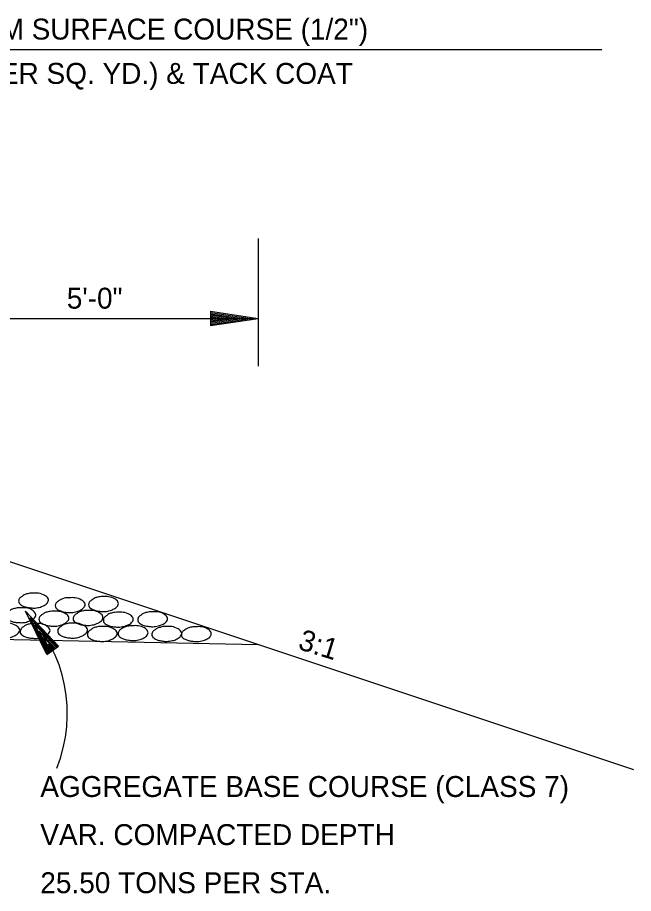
# Model space of a CAD drawing. Extents: x 1035 to 3550, y 35 to 1510.
# Drawn here: x 2578.4 to 2755, y 575.8 to 826.9 of the extents above; entities that cross this region are included whole.
import ezdxf

# ---------------------------------------------------------------- set-up
doc = ezdxf.new("R2010")
doc.units = 0
doc.layers.add('Default', color=7, linetype='Continuous')

msp = doc.modelspace()

# ---------------------------------------------------------------- linework, layer by layer
at = {"layer": 'Default'}
for p, q in [((2745.94, 817.63), (2512.84, 817.63)), ((2647.44, 763.6), (2647.44, 726.95)), ((2633.76, 742.69), (2647.44, 740.65)), ((2633.76, 742.69), (2633.76, 738.59)), ((2633.76, 742.36), (2645.15, 740.65)), ((2633.76, 742), (2642.78, 740.65)), ((2633.76, 741.67), (2640.49, 740.65)), ((2633.76, 741.3), (2638.18, 740.65)), ((2633.76, 740.97), (2635.89, 740.65)), ((2557.51, 740.65), (2647.44, 740.65)), ((2633.76, 738.59), (2647.44, 740.65)), ((2633.76, 739.96), (2638.18, 740.65)), ((2633.76, 739.27), (2642.78, 740.65)), ((2633.76, 738.93), (2645.15, 740.65)), ((2633.76, 739.63), (2640.49, 740.65)), ((2633.76, 740.32), (2635.89, 740.65)), ((2557.51, 677.18), (2755.04, 611.33)), ((2586.85, 644.27), (2580.73, 656.69)), ((2590.23, 646.64), (2580.73, 656.69)), ((2261.14, 654.92), (2647.44, 647.2)), ((2587.13, 644.45), (2582.05, 654.82)), ((2589.95, 646.4), (2582.05, 654.82)), ((2589.66, 646.23), (2583.39, 652.87)), ((2587.43, 644.66), (2583.39, 652.87)), ((2587.72, 644.86), (2584.68, 651)), ((2589.37, 646.01), (2584.68, 651)), ((2589.09, 645.83), (2586.02, 649.1)), ((2588, 645.08), (2586.02, 649.1)), ((2586.85, 644.27), (2590.23, 646.64)), ((2588.8, 645.62), (2587.32, 647.24)), ((2588.28, 645.25), (2587.32, 647.24))]:
    msp.add_line(p, q, dxfattribs=at)
msp.add_arc((2550.89, 627.38), 41.83, 337.9932, 44.4822, dxfattribs=at)
for points in [[(2582.95, 661.87), (2584.48, 661.86), (2586.3, 661.22), (2587.19, 660.39), (2587.31, 659.85), (2586.85, 658.93), (2586.33, 658.54), (2585.33, 658.02), (2583.87, 657.68), (2583.11, 657.6), (2582, 657.71), (2580.74, 657.92), (2579.79, 658.29), (2578.91, 659.02), (2578.76, 659.6), (2579.02, 660.42), (2579.72, 660.95), (2580.36, 661.37), (2581.38, 661.72), (2582.01, 661.86), (2582.95, 661.87)], [(2593.44, 660.57), (2594.95, 660.56), (2596.77, 659.92), (2597.69, 659.06), (2597.83, 658.56), (2597.33, 657.63), (2596.81, 657.21), (2595.84, 656.72), (2594.33, 656.35), (2593.59, 656.3), (2592.46, 656.38), (2591.24, 656.6), (2590.29, 656.99), (2589.4, 657.69), (2589.26, 658.31), (2589.53, 659.09), (2590.21, 659.65), (2590.87, 660.09), (2591.85, 660.42), (2592.47, 660.56), (2593.44, 660.57)], [(2603.01, 660.88), (2604.52, 660.86), (2606.36, 660.24), (2607.23, 659.38), (2607.37, 658.88), (2606.89, 657.93), (2606.38, 657.53), (2605.38, 657.04), (2603.91, 656.67), (2603.15, 656.62), (2602.04, 656.7), (2600.8, 656.92), (2599.83, 657.31), (2598.94, 658.01), (2598.82, 658.59), (2599.1, 659.41), (2599.79, 659.96), (2600.41, 660.39), (2601.42, 660.74), (2602.06, 660.86), (2603.01, 660.88)], [(2579.33, 657.67), (2580.81, 657.66), (2582.65, 657.03), (2583.52, 656.16), (2583.68, 655.66), (2583.21, 654.73), (2582.67, 654.32), (2581.68, 653.84), (2580.22, 653.46), (2579.44, 653.42), (2578.35, 653.48), (2577.1, 653.68), (2576.15, 654.09), (2575.26, 654.79), (2575.12, 655.38), (2575.4, 656.21), (2576.09, 656.77), (2576.7, 657.2), (2577.73, 657.5), (2578.37, 657.66), (2579.33, 657.67)], [(2588.77, 656.68), (2590.28, 656.67), (2592.1, 656.03), (2593.02, 655.17), (2593.16, 654.67), (2592.66, 653.74), (2592.14, 653.32), (2591.17, 652.84), (2589.66, 652.46), (2588.93, 652.41), (2587.79, 652.49), (2586.57, 652.71), (2585.62, 653.1), (2584.73, 653.8), (2584.59, 654.42), (2584.86, 655.2), (2585.54, 655.76), (2586.2, 656.2), (2587.18, 656.53), (2587.8, 656.67), (2588.77, 656.68)], [(2598.59, 656.9), (2600.1, 656.88), (2601.94, 656.26), (2602.82, 655.38), (2602.94, 654.89), (2602.49, 653.97), (2601.96, 653.53), (2600.96, 653.06), (2599.48, 652.7), (2598.75, 652.63), (2597.61, 652.72), (2596.36, 652.92), (2595.44, 653.31), (2594.53, 654.01), (2594.4, 654.61), (2594.68, 655.43), (2595.35, 655.98), (2595.99, 656.43), (2597, 656.74), (2597.64, 656.88), (2598.59, 656.9)], [(2607.26, 656.39), (2608.75, 656.38), (2610.56, 655.75), (2611.47, 654.88), (2611.62, 654.4), (2611.14, 653.46), (2610.59, 653.03), (2609.61, 652.58), (2608.13, 652.22), (2607.38, 652.14), (2606.29, 652.23), (2605.03, 652.44), (2604.09, 652.81), (2603.18, 653.51), (2603.05, 654.12), (2603.33, 654.94), (2604.02, 655.49), (2604.64, 655.93), (2605.65, 656.22), (2606.31, 656.38), (2607.26, 656.39)], [(2617.09, 656.51), (2618.6, 656.5), (2620.44, 655.89), (2621.33, 655.02), (2621.47, 654.53), (2620.98, 653.57), (2620.45, 653.16), (2619.46, 652.71), (2617.98, 652.34), (2617.24, 652.27), (2616.11, 652.35), (2614.87, 652.56), (2613.94, 652.94), (2613.02, 653.66), (2612.91, 654.24), (2613.18, 655.05), (2613.85, 655.61), (2614.5, 656.05), (2615.5, 656.37), (2616.14, 656.5), (2617.09, 656.51)], [(2574.66, 653.27), (2576.17, 653.26), (2577.99, 652.62), (2578.91, 651.76), (2579.05, 651.26), (2578.55, 650.33), (2578.02, 649.91), (2577.06, 649.42), (2575.55, 649.05), (2574.81, 649), (2573.68, 649.08), (2572.46, 649.3), (2571.51, 649.69), (2570.62, 650.39), (2570.48, 651.01), (2570.75, 651.79), (2571.43, 652.35), (2572.09, 652.79), (2573.07, 653.12), (2573.69, 653.26), (2574.66, 653.27)], [(2583.37, 653.19), (2584.88, 653.17), (2586.7, 652.53), (2587.62, 651.67), (2587.76, 651.17), (2587.26, 650.24), (2586.73, 649.82), (2585.77, 649.34), (2584.25, 648.96), (2583.52, 648.92), (2582.38, 648.99), (2581.17, 649.21), (2580.22, 649.6), (2579.33, 650.3), (2579.19, 650.93), (2579.46, 651.7), (2580.14, 652.27), (2580.8, 652.7), (2581.78, 653.03), (2582.4, 653.17), (2583.37, 653.19)], [(2594.12, 653.27), (2595.63, 653.26), (2597.46, 652.62), (2598.38, 651.76), (2598.52, 651.26), (2598.02, 650.33), (2597.49, 649.91), (2596.52, 649.42), (2595.01, 649.05), (2594.28, 649), (2593.14, 649.08), (2591.92, 649.3), (2590.97, 649.69), (2590.09, 650.39), (2589.95, 651.01), (2590.21, 651.79), (2590.9, 652.35), (2591.55, 652.79), (2592.53, 653.12), (2593.16, 653.26), (2594.12, 653.27)], [(2602.64, 652.31), (2604.15, 652.3), (2605.98, 651.66), (2606.89, 650.8), (2607.03, 650.3), (2606.54, 649.37), (2606.01, 648.95), (2605.04, 648.46), (2603.53, 648.09), (2602.8, 648.04), (2601.66, 648.12), (2600.44, 648.34), (2599.49, 648.73), (2598.6, 649.43), (2598.46, 650.05), (2598.73, 650.83), (2599.41, 651.39), (2600.07, 651.83), (2601.05, 652.16), (2601.67, 652.3), (2602.64, 652.31)], [(2611.5, 652.55), (2613.01, 652.53), (2614.82, 651.91), (2615.74, 651.03), (2615.85, 650.55), (2615.39, 649.6), (2614.86, 649.2), (2613.88, 648.71), (2612.39, 648.34), (2611.64, 648.28), (2610.52, 648.39), (2609.29, 648.59), (2608.32, 648.96), (2607.45, 649.69), (2607.29, 650.27), (2607.56, 651.08), (2608.26, 651.64), (2608.9, 652.06), (2609.92, 652.39), (2610.53, 652.53), (2611.5, 652.55)], [(2621.14, 652.31), (2622.64, 652.3), (2624.46, 651.66), (2625.38, 650.82), (2625.51, 650.29), (2625.02, 649.37), (2624.48, 648.95), (2623.53, 648.45), (2622.01, 648.14), (2621.28, 648.03), (2620.14, 648.15), (2618.93, 648.35), (2617.99, 648.74), (2617.09, 649.43), (2616.93, 650.04), (2617.22, 650.85), (2617.9, 651.41), (2618.56, 651.83), (2619.54, 652.14), (2620.16, 652.3), (2621.14, 652.31)], [(2629.63, 652.25), (2631.16, 652.24), (2632.98, 651.6), (2633.87, 650.77), (2633.99, 650.23), (2633.53, 649.31), (2633.01, 648.92), (2632.01, 648.4), (2630.55, 648.06), (2629.79, 647.98), (2628.68, 648.09), (2627.42, 648.3), (2626.47, 648.67), (2625.59, 649.4), (2625.44, 649.98), (2625.7, 650.8), (2626.4, 651.33), (2627.04, 651.75), (2628.06, 652.1), (2628.69, 652.24), (2629.63, 652.25)]]:
    msp.add_spline(points, degree=3, dxfattribs=at)

# ---------------------------------------------------------------- texts
for s, p in [('VAR. ACHM SURFACE COURSE (1/2")', (2535.68, 820.6)), ('(220 LBS. PER SQ. YD.) & TACK COAT', (2530.11, 807.9)), ('5\'-0"', (2592.56, 743.45)), ('AGGREGATE BASE COURSE (CLASS 7)', (2584.97, 603.45)), ('VAR. COMPACTED DEPTH', (2584.97, 589.66)), ('25.50 TONS PER STA.', (2584.97, 575.87))]:
    msp.add_text(s, height=6, dxfattribs=at).set_placement(p)
msp.add_text('3:1', height=6, rotation=342.7185, dxfattribs=at).set_placement((2658.57, 645.94))

doc.saveas('drawing.dxf')
